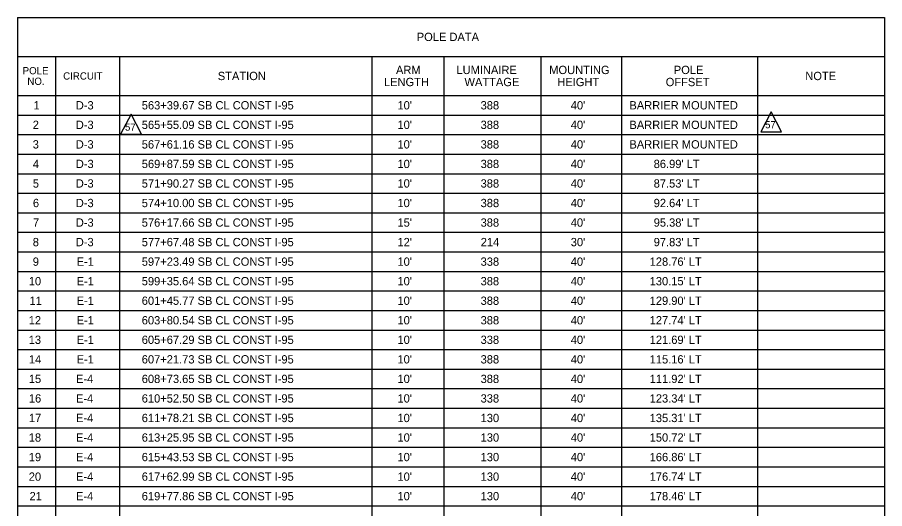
# Model space of a CAD drawing. Extents: x -818.1 to -802.4, y -2221.2 to -2187.7.
# Drawn here: x -817.38 to -810.06, y -2191.84 to -2187.69 of the extents above; entities that cross this region are included whole.
import ezdxf

# ---------------------------------------------------------------- set-up
doc = ezdxf.new("R2010")
doc.units = 0
for name, color, linetype in [('PlotBorder_dp', 7, 'Continuous'), ('SheetBorder_dp', 7, 'Continuous'), ('SheetLines_dp', 7, 'Continuous'), ('TextMinor', 7, 'Continuous'), ('TextTitle', 7, 'Continuous')]:
    doc.layers.add(name, color=color, linetype=linetype)

msp = doc.modelspace()

# ---------------------------------------------------------------- linework, layer by layer
at = {"layer": 'PlotBorder_dp'}
for p, q in [((-817.0539, -2188.0217), (-817.0539, -2195.9417)), ((-817.0539, -2188.0217), (-817.0539, -2195.9417)), ((-816.5139, -2188.0217), (-816.5139, -2195.9417)), ((-816.5139, -2188.0217), (-816.5139, -2195.9417)), ((-814.3839, -2188.0217), (-814.3839, -2193.9617)), ((-814.3839, -2188.0217), (-814.3839, -2195.9417)), ((-813.7764, -2188.0217), (-813.7764, -2195.9417)), ((-813.7764, -2188.0217), (-813.7764, -2195.9417)), ((-812.9589, -2188.0217), (-812.9589, -2195.9417)), ((-812.9589, -2188.0217), (-812.9589, -2195.9417)), ((-812.2764, -2188.0217), (-812.2764, -2195.9417)), ((-812.2764, -2188.0217), (-812.2764, -2195.9417)), ((-811.1289, -2188.0217), (-811.1289, -2195.9417)), ((-811.1289, -2188.0217), (-811.1289, -2195.9417)), ((-817.3764, -2188.3517), (-810.0564, -2188.3517))]:
    msp.add_line(p, q, dxfattribs=at)
at = {"layer": 'SheetLines_dp'}
for p, q in [((-817.3764, -2187.6917), (-810.0564, -2187.6917)), ((-817.3764, -2187.6917), (-817.3764, -2195.9417)), ((-810.0564, -2187.6917), (-810.0564, -2195.9417)), ((-810.0564, -2187.6917), (-810.0564, -2195.9417)), ((-817.3764, -2188.0217), (-810.0564, -2188.0217)), ((-817.3764, -2188.0217), (-810.0564, -2188.0217))]:
    msp.add_line(p, q, dxfattribs=at)
at = {"layer": 'TextMinor'}
for p, q in [((-817.3764, -2188.3517), (-810.0564, -2188.3517)), ((-817.3764, -2188.5167), (-810.0564, -2188.5167)), ((-817.3764, -2188.5167), (-810.0564, -2188.5167)), ((-817.3764, -2188.6817), (-810.0564, -2188.6817)), ((-817.3764, -2188.6817), (-810.0564, -2188.6817)), ((-817.3764, -2188.8467), (-810.0564, -2188.8467)), ((-817.3764, -2188.8467), (-810.0564, -2188.8467)), ((-817.3764, -2189.0117), (-810.0564, -2189.0117)), ((-817.3764, -2189.0117), (-810.0564, -2189.0117)), ((-817.3764, -2189.1767), (-810.0564, -2189.1767)), ((-817.3764, -2189.1767), (-810.0564, -2189.1767)), ((-817.3764, -2189.3417), (-810.0564, -2189.3417)), ((-817.3764, -2189.3417), (-810.0564, -2189.3417)), ((-817.3764, -2189.5067), (-810.0564, -2189.5067)), ((-817.3764, -2189.5067), (-810.0564, -2189.5067)), ((-817.3764, -2189.6717), (-810.0564, -2189.6717)), ((-817.3764, -2189.6717), (-810.0564, -2189.6717)), ((-817.3764, -2189.8367), (-810.0564, -2189.8367)), ((-817.3764, -2189.8367), (-810.0564, -2189.8367)), ((-817.3764, -2190.0017), (-810.0564, -2190.0017)), ((-817.3764, -2190.0017), (-810.0564, -2190.0017)), ((-817.3764, -2190.1667), (-810.0564, -2190.1667)), ((-817.3764, -2190.1667), (-810.0564, -2190.1667)), ((-817.3764, -2190.3317), (-810.0564, -2190.3317)), ((-817.3764, -2190.3317), (-810.0564, -2190.3317)), ((-817.3764, -2190.4967), (-810.0564, -2190.4967)), ((-817.3764, -2190.4967), (-810.0564, -2190.4967)), ((-817.3764, -2190.6617), (-810.0564, -2190.6617)), ((-817.3764, -2190.6617), (-810.0564, -2190.6617)), ((-817.3764, -2190.8267), (-810.0564, -2190.8267)), ((-817.3764, -2190.8267), (-810.0564, -2190.8267)), ((-817.3764, -2190.9917), (-810.0564, -2190.9917)), ((-817.3764, -2190.9917), (-810.0564, -2190.9917)), ((-817.3764, -2191.1567), (-810.0564, -2191.1567)), ((-817.3764, -2191.1567), (-810.0564, -2191.1567)), ((-817.3764, -2191.3217), (-810.0564, -2191.3217)), ((-817.3764, -2191.3217), (-810.0564, -2191.3217)), ((-817.3764, -2191.4867), (-810.0564, -2191.4867)), ((-817.3764, -2191.4867), (-810.0564, -2191.4867)), ((-817.3764, -2191.6517), (-810.0564, -2191.6517)), ((-817.3764, -2191.6517), (-810.0564, -2191.6517)), ((-817.3764, -2191.8167), (-810.0564, -2191.8167)), ((-817.3764, -2191.8167), (-810.0564, -2191.8167))]:
    msp.add_line(p, q, dxfattribs=at)
at = {"layer": 'TextTitle'}
for points in [[(-816.4166, -2188.5096), (-816.5046, -2188.6791), (-816.3286, -2188.6791)], [(-811.0144, -2188.4885), (-811.1024, -2188.6581), (-810.9263, -2188.6581)]]:
    msp.add_lwpolyline(points, close=True, dxfattribs=at)

# ---------------------------------------------------------------- texts
at = {"layer": 'SheetBorder_dp'}
for s, height, p in [('POLE DATA', 0.07, (-814.0053, -2187.8917)), ('POLE', 0.06125, (-817.3318, -2188.1727)), ('CIRCUIT', 0.06125, (-816.9898, -2188.2173)), ('STATION', 0.07, (-815.6847, -2188.2217)), ('ARM', 0.07, (-814.1806, -2188.1707)), ('LUMINAIRE', 0.07, (-813.6703, -2188.1707)), ('MOUNTING', 0.07, (-812.8873, -2188.1707)), ('POLE', 0.07, (-811.8359, -2188.1707)), ('NOTE', 0.07, (-810.7259, -2188.2217)), ('NO.', 0.06125, (-817.2918, -2188.2619)), ('LENGTH', 0.07, (-814.2821, -2188.2727)), ('WATTAGE', 0.07, (-813.6025, -2188.2727)), ('HEIGHT', 0.07, (-812.8191, -2188.2727)), ('OFFSET', 0.07, (-811.9041, -2188.2727)), ('1', 0.07, (-817.2398, -2188.4692)), ('D-3', 0.07, (-816.8831, -2188.4692)), ('563+39.67 SB CL CONST I-95', 0.07, (-816.3263, -2188.4692)), ("10'", 0.07, (-814.1681, -2188.4692)), ('388', 0.07, (-813.4665, -2188.4692)), ("40'", 0.07, (-812.7056, -2188.4692)), ('BARRIER MOUNTED', 0.07, (-812.2105, -2188.4692)), ('2', 0.07, (-817.2465, -2188.6342)), ('D-3', 0.07, (-816.8831, -2188.6342)), ('565+55.09 SB CL CONST I-95', 0.07, (-816.3263, -2188.6342)), ("10'", 0.07, (-814.1681, -2188.6342)), ('388', 0.07, (-813.4665, -2188.6342)), ("40'", 0.07, (-812.7056, -2188.6342)), ('BARRIER MOUNTED', 0.07, (-812.2105, -2188.6342)), ('3', 0.07, (-817.2466, -2188.7992)), ('D-3', 0.07, (-816.8831, -2188.7992)), ('567+61.16 SB CL CONST I-95', 0.07, (-816.3263, -2188.7992)), ("10'", 0.07, (-814.1681, -2188.7992)), ('388', 0.07, (-813.4665, -2188.7992)), ("40'", 0.07, (-812.7056, -2188.7992)), ('BARRIER MOUNTED', 0.07, (-812.2105, -2188.7992)), ('4', 0.07, (-817.2452, -2188.9642)), ('D-3', 0.07, (-816.8831, -2188.9642)), ('569+87.59 SB CL CONST I-95', 0.07, (-816.3263, -2188.9642)), ("10'", 0.07, (-814.1681, -2188.9642)), ('388', 0.07, (-813.4665, -2188.9642)), ("40'", 0.07, (-812.7056, -2188.9642)), ("86.99' LT", 0.07, (-812.0057, -2188.9642)), ('5', 0.07, (-817.2457, -2189.1292)), ('D-3', 0.07, (-816.8831, -2189.1292)), ('571+90.27 SB CL CONST I-95', 0.07, (-816.3263, -2189.1292)), ("10'", 0.07, (-814.1681, -2189.1292)), ('388', 0.07, (-813.4665, -2189.1292)), ("40'", 0.07, (-812.7056, -2189.1292)), ("87.53' LT", 0.07, (-812.0057, -2189.1292)), ('6', 0.07, (-817.2451, -2189.2942)), ('D-3', 0.07, (-816.8831, -2189.2942)), ('574+10.00 SB CL CONST I-95', 0.07, (-816.3263, -2189.2942)), ("10'", 0.07, (-814.1681, -2189.2942)), ('388', 0.07, (-813.4665, -2189.2942)), ("40'", 0.07, (-812.7056, -2189.2942)), ("92.64' LT", 0.07, (-812.0057, -2189.2942)), ('7', 0.07, (-817.2445, -2189.4592)), ('D-3', 0.07, (-816.8831, -2189.4592)), ('576+17.66 SB CL CONST I-95', 0.07, (-816.3263, -2189.4592)), ("15'", 0.07, (-814.1681, -2189.4592)), ('388', 0.07, (-813.4665, -2189.4592)), ("40'", 0.07, (-812.7056, -2189.4592)), ("95.38' LT", 0.07, (-812.0057, -2189.4592)), ('8', 0.07, (-817.2463, -2189.6242)), ('D-3', 0.07, (-816.8831, -2189.6242)), ('577+67.48 SB CL CONST I-95', 0.07, (-816.3263, -2189.6242)), ("12'", 0.07, (-814.1681, -2189.6242)), ('214', 0.07, (-813.4654, -2189.6242)), ("30'", 0.07, (-812.7056, -2189.6242)), ("97.83' LT", 0.07, (-812.0057, -2189.6242)), ('9', 0.07, (-817.2462, -2189.7892)), ('E-1', 0.07, (-816.8763, -2189.7892)), ('597+23.49 SB CL CONST I-95', 0.07, (-816.3263, -2189.7892)), ("10'", 0.07, (-814.1681, -2189.7892)), ('338', 0.07, (-813.4665, -2189.7892)), ("40'", 0.07, (-812.7056, -2189.7892)), ("128.76' LT", 0.07, (-812.0396, -2189.7892)), ('10', 0.07, (-817.2798, -2189.9542)), ('E-1', 0.07, (-816.8763, -2189.9542)), ('599+35.64 SB CL CONST I-95', 0.07, (-816.3263, -2189.9542)), ("10'", 0.07, (-814.1681, -2189.9542)), ('388', 0.07, (-813.4665, -2189.9542)), ("40'", 0.07, (-812.7056, -2189.9542)), ("130.15' LT", 0.07, (-812.0396, -2189.9542)), ('11', 0.07, (-817.2737, -2190.1192)), ('E-1', 0.07, (-816.8763, -2190.1192)), ('601+45.77 SB CL CONST I-95', 0.07, (-816.3263, -2190.1192)), ("10'", 0.07, (-814.1681, -2190.1192)), ('388', 0.07, (-813.4665, -2190.1192)), ("40'", 0.07, (-812.7056, -2190.1192)), ("129.90' LT", 0.07, (-812.0396, -2190.1192)), ('12', 0.07, (-817.2804, -2190.2842)), ('E-1', 0.07, (-816.8763, -2190.2842)), ('603+80.54 SB CL CONST I-95', 0.07, (-816.3263, -2190.2842)), ("10'", 0.07, (-814.1681, -2190.2842)), ('388', 0.07, (-813.4665, -2190.2842)), ("40'", 0.07, (-812.7056, -2190.2842)), ("127.74' LT", 0.07, (-812.0396, -2190.2842)), ('13', 0.07, (-817.2804, -2190.4492)), ('E-1', 0.07, (-816.8763, -2190.4492)), ('605+67.29 SB CL CONST I-95', 0.07, (-816.3263, -2190.4492)), ("10'", 0.07, (-814.1681, -2190.4492)), ('338', 0.07, (-813.4665, -2190.4492)), ("40'", 0.07, (-812.7056, -2190.4492)), ("121.69' LT", 0.07, (-812.0396, -2190.4492)), ('14', 0.07, (-817.279, -2190.6142)), ('E-1', 0.07, (-816.8763, -2190.6142)), ('607+21.73 SB CL CONST I-95', 0.07, (-816.3263, -2190.6142)), ("10'", 0.07, (-814.1681, -2190.6142)), ('388', 0.07, (-813.4665, -2190.6142)), ("40'", 0.07, (-812.7056, -2190.6142)), ("115.16' LT", 0.07, (-812.0396, -2190.6142)), ('15', 0.07, (-817.2795, -2190.7792)), ('E-4', 0.07, (-816.8817, -2190.7792)), ('608+73.65 SB CL CONST I-95', 0.07, (-816.3263, -2190.7792)), ("10'", 0.07, (-814.1681, -2190.7792)), ('388', 0.07, (-813.4665, -2190.7792)), ("40'", 0.07, (-812.7056, -2190.7792)), ("111.92' LT", 0.07, (-812.0396, -2190.7792)), ('16', 0.07, (-817.279, -2190.9442)), ('E-4', 0.07, (-816.8817, -2190.9442)), ('610+52.50 SB CL CONST I-95', 0.07, (-816.3263, -2190.9442)), ("10'", 0.07, (-814.1681, -2190.9442)), ('338', 0.07, (-813.4665, -2190.9442)), ("40'", 0.07, (-812.7056, -2190.9442)), ("123.34' LT", 0.07, (-812.0396, -2190.9442)), ('17', 0.07, (-817.2784, -2191.1092)), ('E-4', 0.07, (-816.8817, -2191.1092)), ('611+78.21 SB CL CONST I-95', 0.07, (-816.3263, -2191.1092)), ("10'", 0.07, (-814.1681, -2191.1092)), ('130', 0.07, (-813.4662, -2191.1092)), ("40'", 0.07, (-812.7056, -2191.1092)), ("135.31' LT", 0.07, (-812.0396, -2191.1092)), ('18', 0.07, (-817.2802, -2191.2742)), ('E-4', 0.07, (-816.8817, -2191.2742)), ('613+25.95 SB CL CONST I-95', 0.07, (-816.3263, -2191.2742)), ("10'", 0.07, (-814.1681, -2191.2742)), ('130', 0.07, (-813.4662, -2191.2742)), ("40'", 0.07, (-812.7056, -2191.2742)), ("150.72' LT", 0.07, (-812.0396, -2191.2742)), ('19', 0.07, (-817.28, -2191.4392)), ('E-4', 0.07, (-816.8817, -2191.4392)), ('615+43.53 SB CL CONST I-95', 0.07, (-816.3263, -2191.4392)), ("10'", 0.07, (-814.1681, -2191.4392)), ('130', 0.07, (-813.4662, -2191.4392)), ("40'", 0.07, (-812.7056, -2191.4392)), ("166.86' LT", 0.07, (-812.0396, -2191.4392)), ('20', 0.07, (-817.2798, -2191.6042)), ('E-4', 0.07, (-816.8817, -2191.6042)), ('617+62.99 SB CL CONST I-95', 0.07, (-816.3263, -2191.6042)), ("10'", 0.07, (-814.1681, -2191.6042)), ('130', 0.07, (-813.4662, -2191.6042)), ("40'", 0.07, (-812.7056, -2191.6042)), ("176.74' LT", 0.07, (-812.0396, -2191.6042)), ('21', 0.07, (-817.2737, -2191.7692)), ('E-4', 0.07, (-816.8817, -2191.7692)), ('619+77.86 SB CL CONST I-95', 0.07, (-816.3263, -2191.7692)), ("10'", 0.07, (-814.1681, -2191.7692)), ('130', 0.07, (-813.4662, -2191.7692)), ("40'", 0.07, (-812.7056, -2191.7692)), ("178.46' LT", 0.07, (-812.0396, -2191.7692))]:
    msp.add_text(s, height=height, dxfattribs=at).set_placement(p)
at = {"layer": 'TextTitle'}
for p in [(-816.4673, -2188.6489), (-811.0651, -2188.6279)]:
    msp.add_text('57', height=0.06, dxfattribs=at).set_placement(p)

doc.saveas('drawing.dxf')
